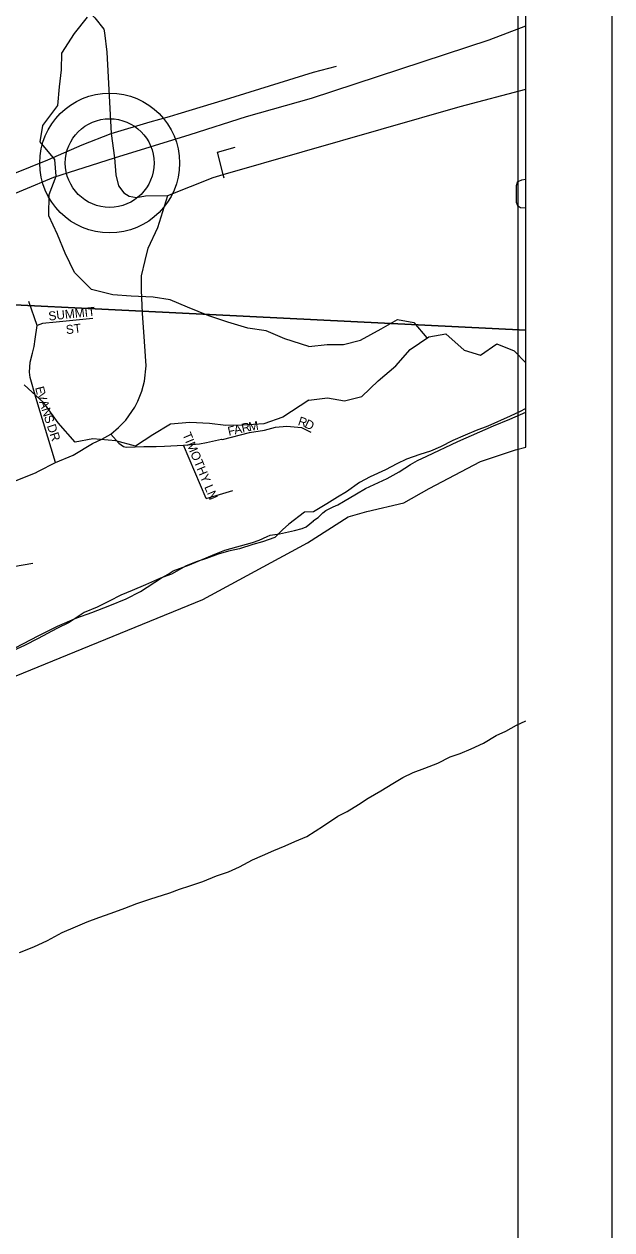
# Model space of a CAD drawing. Extents: x 0 to 34, y 0 to 22.
# Drawn here: x 8.374 to 9, y 14.797 to 16.08 of the extents above; entities that cross this region are included whole.
import ezdxf

# ---------------------------------------------------------------- set-up
doc = ezdxf.new("R2010")
doc.units = 0
for name, color, linetype in [('GM_X_Airport_Class_3', 7, 'Continuous'), ('GM_X_County', 7, 'Continuous'), ('GM_X_County_Road', 7, 'Continuous'), ('GM_X_Major_River', 7, 'Continuous'), ('GM_X_Minor_River', 7, 'Continuous'), ('GM_X_Section', 7, 'Continuous'), ('GM_X_Township', 7, 'Continuous'), ('GM_X_Township_ROW', 7, 'Continuous'), ('GM_X_Township_Subdivision', 7, 'Continuous'), ('GM_X_Township_Subdivision_Text', 7, 'Continuous'), ('GM_X_Unincorporated', 7, 'Continuous'), ('GM_X_Unincorporated_Location', 7, 'Continuous'), ('GM_X_US_Route', 7, 'Continuous'), ('SH_Data', 7, 'Continuous')]:
    doc.layers.add(name, color=color, linetype=linetype)

msp = doc.modelspace()

# ---------------------------------------------------------------- linework, layer by layer
at = {"layer": 'GM_X_Airport_Class_3'}
msp.add_line((8.9084, 15.885), (8.9084, 15.915), dxfattribs=at)
msp.add_lwpolyline([(8.9084, 15.915), (8.9038, 15.9144), (8.9005, 15.913), (8.8993, 15.9117), (8.8983, 15.9082), (8.8982, 15.891), (8.8994, 15.8873), (8.9026, 15.8851), (8.9084, 15.885)], dxfattribs=at)
at = {"layer": 'GM_X_County'}
for points in [[(8.9084, 15.63), (8.9084, 20.8908), (2.1084, 20.8908), (2.1084, 19.9847)], [(5.8119, 14.8141), (6.1284, 14.8081), (6.2942, 14.8107), (6.3434, 14.8225), (6.4918, 14.8467), (6.6258, 14.8615), (6.8567, 14.9043), (7.3029, 15.0101), (7.3665, 15.0352), (7.8253, 15.188), (8.2132, 15.3314), (8.3328, 15.3731), (8.5648, 15.4679), (8.676, 15.5284), (8.7195, 15.5558), (8.7393, 15.5616), (8.7787, 15.5707), (8.8056, 15.586), (8.8602, 15.6149), (8.8974, 15.6271), (8.9084, 15.63)]]:
    msp.add_lwpolyline(points, dxfattribs=at)
at = {"layer": 'GM_X_County_Road'}
for points in [[(7.8426, 16.4384), (7.879, 16.4205), (7.9624, 16.3946), (8.051, 16.3683), (8.0855, 16.3577), (8.1199, 16.3444), (8.1703, 16.3265), (8.1858, 16.3113), (8.1953, 16.2991), (8.2014, 16.2668), (8.2131, 16.2486), (8.3025, 16.1976), (8.3173, 16.1892), (8.3362, 16.182), (8.3513, 16.1774), (8.3768, 16.1545), (8.4092, 16.1276), (8.4334, 16.1031), (8.4496, 16.0872), (8.4594, 16.0751), (8.4601, 16.0712), (8.4624, 16.0506), (8.467, 15.9639), (8.4705, 15.9381)], [(8.5293, 15.9822), (8.5385, 15.9848), (8.5888, 16), (8.6823, 16.0293), (8.707, 16.0356)], [(8.5274, 15.8979), (8.5756, 15.9172), (8.5862, 15.9202), (8.8384, 15.9928), (8.9084, 16.011)], [(8.467, 15.9639), (8.5085, 15.9764), (8.5293, 15.9822)], [(8.0503, 15.7803), (8.0874, 15.7928), (8.1452, 15.8216), (8.2179, 15.8552), (8.2805, 15.8833), (8.2998, 15.8934), (8.3423, 15.9128), (8.3998, 15.9358), (8.4361, 15.9518), (8.467, 15.9639)], [(8.4705, 15.9381), (8.4705, 15.9381), (8.472, 15.9199), (8.475, 15.9082), (8.4806, 15.9009), (8.4861, 15.8974), (8.4942, 15.8958), (8.5036, 15.8977), (8.5274, 15.8979)], [(8.3897, 15.6045), (8.408, 15.6137), (8.4267, 15.6215), (8.4473, 15.6341), (8.4571, 15.6385), (8.4669, 15.6439), (8.4748, 15.651), (8.4826, 15.6588), (8.4924, 15.6728), (8.4956, 15.679), (8.4998, 15.6898), (8.5025, 15.7005), (8.5045, 15.7166), (8.5027, 15.7426), (8.5005, 15.7726), (8.4993, 15.7971), (8.4995, 15.8123), (8.5031, 15.8288), (8.5063, 15.8418), (8.5167, 15.8638), (8.5274, 15.8979)], [(8.3426, 15.5854), (8.3864, 15.6029), (8.3897, 15.6045)]]:
    msp.add_lwpolyline(points, dxfattribs=at)
at = {"layer": 'GM_X_Major_River'}
for points in [[(8.9084, 15.6713), (8.9018, 15.6678), (8.8919, 15.6632), (8.8681, 15.6525), (8.8556, 15.6479), (8.8439, 15.643), (8.8307, 15.6372), (8.8175, 15.6304), (8.8069, 15.6258), (8.7955, 15.6224), (8.7815, 15.6174), (8.771, 15.6124), (8.7589, 15.606), (8.7426, 15.5987), (8.7313, 15.5926), (8.7177, 15.5827), (8.7078, 15.577), (8.6965, 15.5698), (8.6825, 15.5614), (8.6727, 15.561)], [(8.6727, 15.561), (8.6563, 15.548), (8.6495, 15.542), (8.6413, 15.5341), (8.6281, 15.5295), (8.6178, 15.5265), (8.6035, 15.5219), (8.5921, 15.5193), (8.5808, 15.5162), (8.5687, 15.5117), (8.5585, 15.5083), (8.5468, 15.5037), (8.5312, 15.495), (8.5195, 15.4908), (8.5036, 15.4836), (8.4893, 15.4776), (8.4775, 15.4727), (8.4651, 15.4662), (8.4522, 15.4598), (8.4382, 15.4541), (8.4223, 15.4435), (8.4091, 15.437), (8.3894, 15.4264), (8.375, 15.4192), (8.3592, 15.412)], [(8.6752, 15.2158), (8.6929, 15.227), (8.7084, 15.2373), (8.7182, 15.2423), (8.7303, 15.2499), (8.7405, 15.2567), (8.7541, 15.2644), (8.7669, 15.272), (8.7775, 15.2784), (8.7885, 15.2838), (8.801, 15.2884), (8.8146, 15.2937), (8.8278, 15.3006), (8.8384, 15.304), (8.8501, 15.309), (8.8634, 15.3151), (8.877, 15.3231), (8.8872, 15.328), (8.8985, 15.3341), (8.9084, 15.339)], [(8.3697, 15.0923), (8.3848, 15.0983), (8.3995, 15.1052), (8.415, 15.1135), (8.429, 15.1196), (8.4415, 15.1249), (8.454, 15.1294), (8.4672, 15.1343), (8.4816, 15.1396), (8.4945, 15.1446), (8.5084, 15.1491), (8.5296, 15.1559), (8.5398, 15.1597), (8.5508, 15.1631), (8.5648, 15.1677), (8.5792, 15.1738), (8.592, 15.1783), (8.6038, 15.1836), (8.6174, 15.1908), (8.6283, 15.1954), (8.6401, 15.2007), (8.6522, 15.206), (8.6624, 15.2105), (8.6752, 15.2158)]]:
    msp.add_lwpolyline(points, dxfattribs=at)
at = {"layer": 'GM_X_Minor_River'}
for points in [[(8.6776, 15.7372), (8.6518, 15.7454), (8.6322, 15.7538), (8.6125, 15.7569), (8.5913, 15.7631), (8.5709, 15.77), (8.5482, 15.7792), (8.53, 15.7868), (8.5119, 15.7899), (8.4884, 15.7908), (8.4687, 15.7924), (8.446, 15.7978), (8.4279, 15.8161), (8.4182, 15.8366), (8.4099, 15.8564), (8.4009, 15.8762), (8.401, 15.8989), (8.4087, 15.9187), (8.4072, 15.9361), (8.3914, 15.9552), (8.3945, 15.9726), (8.4105, 15.9938), (8.4121, 16.0136), (8.4144, 16.0318), (8.4145, 16.0493), (8.4282, 16.0705), (8.4419, 16.0879)], [(8.6776, 15.7372), (8.6968, 15.7394), (8.7142, 15.7394), (8.7324, 15.744), (8.7544, 15.7561), (8.7718, 15.766), (8.7892, 15.7629), (8.8031, 15.7463)], [(8.6776, 15.6803), (8.6975, 15.6825), (8.7156, 15.6795), (8.7338, 15.684), (8.7512, 15.7007), (8.7702, 15.7166), (8.7854, 15.7341), (8.8051, 15.7477), (8.8232, 15.7507), (8.8429, 15.7333), (8.8603, 15.728), (8.8777, 15.7401), (8.8959, 15.7325), (8.9084, 15.7199)], [(8.6776, 15.6803), (8.6499, 15.6619), (8.6295, 15.6551), (8.6075, 15.6537), (8.5893, 15.653), (8.5719, 15.6553), (8.5507, 15.6562), (8.5302, 15.6547), (8.5113, 15.6434), (8.493, 15.6313), (8.4719, 15.6367), (8.4476, 15.6391), (8.4287, 15.6354), (8.4106, 15.6559), (8.3955, 15.6772), (8.3744, 15.6963)]]:
    msp.add_lwpolyline(points, dxfattribs=at)
at = {"layer": 'GM_X_Section'}
for p, q in [((8.9084, 15.7545), (8.9084, 16.7577)), ((8.9084, 15.6672), (8.9084, 15.7545))]:
    msp.add_line(p, q, dxfattribs=at)
for points in [[(8.9084, 16.7577), (7.9583, 16.8099), (7.9053, 15.8044), (8.9084, 15.7545)], [(8.9084, 15.7545), (7.9053, 15.8044)], [(8.3574, 15.4127), (8.3893, 15.4293), (8.4101, 15.4395), (8.4306, 15.4486), (8.4465, 15.4543), (8.4658, 15.4615), (8.4829, 15.4687), (8.4984, 15.4766), (8.5208, 15.491), (8.5276, 15.4948), (8.5329, 15.4986), (8.5504, 15.505), (8.5773, 15.5163), (8.5879, 15.5205), (8.6174, 15.5288), (8.6246, 15.5311), (8.633, 15.5352), (8.6364, 15.5364), (8.6462, 15.5379), (8.6622, 15.5413), (8.6705, 15.5436), (8.6747, 15.5455), (8.6825, 15.5518), (8.6826, 15.5519), (8.6826, 15.5522), (8.6874, 15.5551), (8.6923, 15.5601), (8.6957, 15.5627), (8.6991, 15.5646), (8.7033, 15.5665), (8.7082, 15.5688), (8.7143, 15.5722), (8.7283, 15.5806), (8.7378, 15.5863), (8.7469, 15.5904), (8.7609, 15.5969), (8.7737, 15.6037), (8.7798, 15.6079), (8.7855, 15.6117), (8.7931, 15.6158), (8.8029, 15.6204), (8.8359, 15.6363), (8.8741, 15.6527), (8.8915, 15.6599), (8.9084, 15.6672)]]:
    msp.add_lwpolyline(points, dxfattribs=at)
at = {"layer": 'GM_X_Township'}
for points in [[(8.9084, 15.63), (8.9084, 20.8908), (5.9855, 20.8908)], [(5.8119, 14.8141), (6.1284, 14.8081), (6.2942, 14.8107), (6.3434, 14.8225), (6.4918, 14.8467), (6.6258, 14.8615), (6.8567, 14.9043), (7.3029, 15.0101), (7.3665, 15.0352), (7.8253, 15.188), (8.2132, 15.3314), (8.3328, 15.3731), (8.5648, 15.4679), (8.676, 15.5284), (8.7195, 15.5558), (8.7393, 15.5616), (8.7787, 15.5707), (8.8056, 15.586), (8.8602, 15.6149), (8.8974, 15.6271), (8.9084, 15.63)]]:
    msp.add_lwpolyline(points, dxfattribs=at)
at = {"layer": 'GM_X_Township_ROW'}
msp.add_lwpolyline([(8.3882, 15.7597), (8.3793, 15.7852)], dxfattribs=at)
at = {"layer": 'GM_X_Township_Subdivision'}
for points in [[(8.5802, 15.9439), (8.599, 15.9494)], [(8.5872, 15.9163), (8.5862, 15.9202), (8.5802, 15.9439)], [(8.408, 15.6137), (8.387, 15.6828), (8.381, 15.7043), (8.3803, 15.7099), (8.381, 15.7206), (8.3833, 15.7301), (8.385, 15.7372), (8.3862, 15.745), (8.3882, 15.7597)], [(8.4474, 15.7669), (8.4086, 15.7632), (8.3939, 15.7619), (8.3882, 15.7597)], [(8.4669, 15.6439), (8.4753, 15.6344), (8.4801, 15.6307), (8.4815, 15.6305)], [(8.5686, 15.6352), (8.5846, 15.6387), (8.5856, 15.6383), (8.6142, 15.6459), (8.6304, 15.6481), (8.6421, 15.6515), (8.654, 15.6523), (8.6697, 15.6512), (8.6796, 15.6461)], [(8.4815, 15.6305), (8.4838, 15.6301), (8.502, 15.6307), (8.5151, 15.631)], [(8.5151, 15.631), (8.5238, 15.6312), (8.544, 15.6321), (8.5612, 15.6336), (8.5686, 15.6352)], [(8.5681, 15.5755), (8.544, 15.6321)], [(8.5681, 15.5755), (8.5967, 15.5841)], [(8.363, 15.5031), (8.3838, 15.5067)]]:
    msp.add_lwpolyline(points, dxfattribs=at)
at = {"layer": 'GM_X_Unincorporated'}
for radius in [0.0744, 0.0472]:
    msp.add_circle((8.4655, 15.9325), radius, dxfattribs=at)
at = {"layer": 'GM_X_Unincorporated_Location'}
msp.add_line((8.4655, 15.9325), (8.4655, 15.9325), dxfattribs=at)
at = {"layer": 'GM_X_US_Route'}
msp.add_lwpolyline([(8.0072, 15.7345), (8.0522, 15.7561), (8.1668, 15.8115), (8.2644, 15.8594), (8.3413, 15.8906), (8.406, 15.9174), (8.4705, 15.9381), (8.5513, 15.963), (8.6112, 15.9821), (8.6803, 16.0015), (8.8695, 16.0638), (8.9084, 16.0785)], dxfattribs=at)
at = {"layer": 'SH_Data'}
for p, q in [((9, 21), (9, 14)), ((8.9, 20.9), (8.9, 14.1))]:
    msp.add_line(p, q, dxfattribs=at)

# ---------------------------------------------------------------- texts
at = {"layer": 'GM_X_Township_Subdivision_Text'}
for s, rotation, p in [('SUMMIT', 6.1156, (8.4008, 15.7648)), ('ST', 7.1242, (8.4195, 15.7503)), ('E', 284.187, (8.3861, 15.6935)), ('V', 286.3693, (8.3878, 15.6866)), ('A', 287.8592, (8.3903, 15.6784)), ('N', 287.913, (8.3928, 15.6704)), ('S', 287.9204, (8.3954, 15.6625)), ('R', 12.6786, (8.6069, 15.6455)), ('M', 9.3283, (8.6141, 15.6471)), ('R', 341.9782, (8.6652, 15.6539)), ('D', 334.4615, (8.6721, 15.6517)), ('DR', 288.4364, (8.3986, 15.6528)), ('TIMOTHY LN', 292.6695, (8.5427, 15.6437)), ('F', 12.7277, (8.5923, 15.6422)), ('A', 12.7334, (8.5988, 15.6436))]:
    msp.add_text(s, height=0.00947, rotation=rotation, dxfattribs=at).set_placement(p)

doc.saveas('drawing.dxf')
